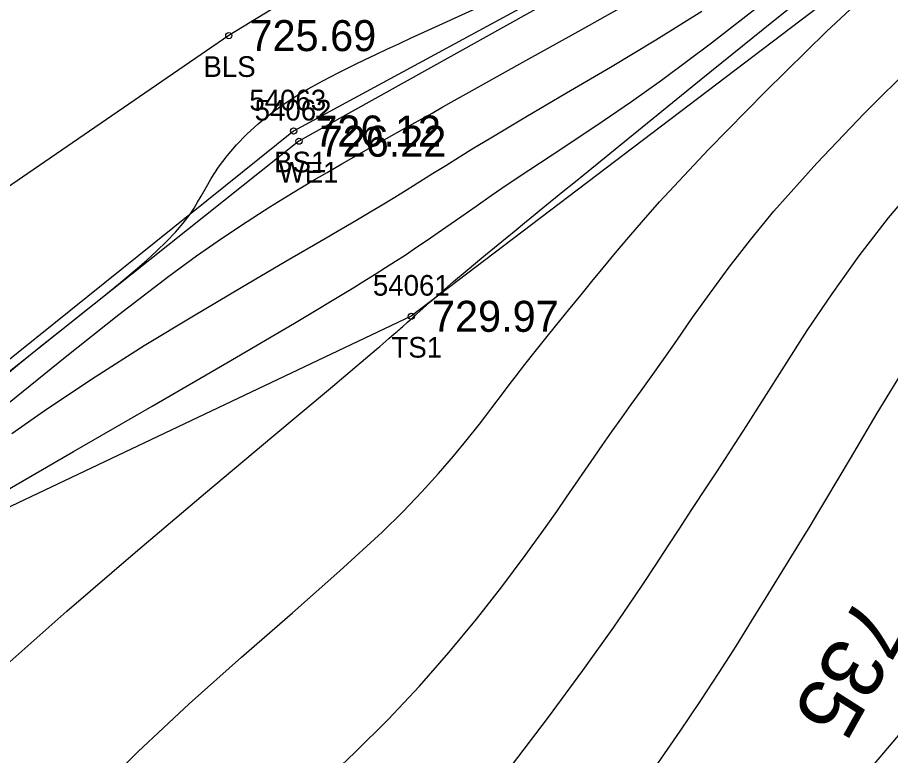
# Model space of a CAD drawing. Extents: x 1378535 to 1380697, y 997729 to 1000024.
# Drawn here: x 1379594.96 to 1379637.21, y 998876.8 to 998912.53 of the extents above; entities that cross this region are included whole.
import ezdxf

# ---------------------------------------------------------------- set-up
doc = ezdxf.new("R2010")
doc.units = 0
for name, color, linetype in [('RD_DTM_BkLn1', 7, 'Continuous'), ('RD_DTM_BkLn2', 7, 'Continuous'), ('RD_DTM_BkLn_txCode', 7, 'Continuous'), ('RD_DTM_Major1', 7, 'Continuous'), ('RD_DTM_Major1_Lbl', 7, 'Continuous'), ('RD_DTM_Minor1', 7, 'Continuous'), ('RD_EX_H2O', 7, 'Continuous'), ('RD_EX_H2O_txCode', 7, 'Continuous'), ('RD_EX_TX_H2O_ELEV', 7, 'Continuous'), ('RD_EX_TX_Misc_ELEV', 7, 'Continuous'), ('RD_SMD_Locator', 7, 'Continuous')]:
    doc.layers.add(name, color=color, linetype=linetype)

msp = doc.modelspace()

# ---------------------------------------------------------------- linework, layer by layer
at = {"layer": 'RD_DTM_BkLn1'}
msp.add_lwpolyline([(1379671.069, 998947.908), (1379636.827, 998930.955), (1379605.186, 998911.649), (1379580.097, 998894.437), (1379553.453, 998877.652)], dxfattribs=at)
at = {"layer": 'RD_DTM_BkLn2'}
for points in [[(1379671.775, 998943.782), (1379640.108, 998924.255), (1379608.322, 998907.031), (1379585.019, 998888.315), (1379555.8, 998870.974), (1379525.725, 998858.388)], [(1379674.341, 998938.659), (1379643.601, 998920.545), (1379614.018, 998898.062), (1379587.543, 998885.495), (1379561.757, 998869.277), (1379529.754, 998852.608)], [(1379679.56, 998932.013), (1379659.421, 998903.53), (1379632.901, 998872.262), (1379612.083, 998858.812), (1379587.234, 998833.516)]]:
    msp.add_lwpolyline(points, dxfattribs=at)
at = {"layer": 'RD_DTM_Major1'}
msp.add_lwpolyline([(1379594.297, 998881.082), (1379597.352, 998883.788), (1379600.677, 998886.651), (1379604.054, 998889.511), (1379607.268, 998892.208), (1379610.102, 998894.583), (1379612.339, 998896.473), (1379612.495, 998896.607), (1379612.646, 998896.737), (1379612.791, 998896.861), (1379612.93, 998896.982), (1379613.064, 998897.098), (1379613.193, 998897.211), (1379613.262, 998897.271), (1379613.33, 998897.33), (1379613.396, 998897.388), (1379613.461, 998897.445), (1379613.525, 998897.501), (1379613.587, 998897.556), (1379613.838, 998897.778), (1379614.071, 998897.986), (1379614.293, 998898.185), (1379614.722, 998898.569), (1379614.939, 998898.762), (1379615.476, 998899.233), (1379616.067, 998899.742), (1379616.717, 998900.294), (1379617.433, 998900.893), (1379618.221, 998901.544), (1379619.086, 998902.253), (1379619.501, 998902.591), (1379619.933, 998902.943), (1379620.386, 998903.311), (1379621.357, 998904.098), (1379621.879, 998904.521), (1379624.757, 998906.863), (1379628.047, 998909.536), (1379631.542, 998912.36), (1379635.038, 998915.154)], dxfattribs=at)
at = {"layer": 'RD_DTM_Minor1'}
for points in [[(1379598.427, 998874.6), (1379600.781, 998876.982), (1379603.271, 998879.309), (1379605.797, 998881.56), (1379608.261, 998883.71), (1379610.563, 998885.737), (1379612.604, 998887.616), (1379613.618, 998888.615), (1379614.526, 998889.561), (1379615.339, 998890.455), (1379616.068, 998891.3), (1379616.724, 998892.097), (1379617.317, 998892.849), (1379617.624, 998893.246), (1379617.918, 998893.632), (1379618.482, 998894.381), (1379618.759, 998894.747), (1379619.037, 998895.112), (1379619.515, 998895.729), (1379620.009, 998896.354), (1379620.524, 998896.997), (1379621.063, 998897.664), (1379621.631, 998898.363), (1379622.232, 998899.103), (1379622.75, 998899.741), (1379623.301, 998900.417), (1379623.897, 998901.135), (1379624.545, 998901.901), (1379625.255, 998902.721), (1379626.038, 998903.6), (1379628.408, 998906.142), (1379631.155, 998908.945), (1379634.11, 998911.841), (1379637.107, 998914.66)], [(1379594.555, 998893.892), (1379597.263, 998896.079), (1379599.865, 998898.15), (1379602.285, 998900.006), (1379603.629, 998900.986), (1379604.888, 998901.864), (1379606.068, 998902.652), (1379607.177, 998903.363), (1379608.222, 998904.008), (1379609.211, 998904.599), (1379609.942, 998905.026), (1379610.655, 998905.438), (1379611.365, 998905.841), (1379612.084, 998906.247), (1379612.824, 998906.663), (1379613.598, 998907.098), (1379614.055, 998907.355), (1379614.53, 998907.623), (1379615.026, 998907.903), (1379615.547, 998908.197), (1379616.095, 998908.505), (1379616.674, 998908.83), (1379619.272, 998910.279), (1379622.237, 998911.933), (1379625.404, 998913.714)], [(1379593.851, 998889.31), (1379597.678, 998891.524), (1379601.473, 998893.715), (1379605.085, 998895.811), (1379608.363, 998897.735), (1379611.158, 998899.415), (1379611.726, 998899.765), (1379612.262, 998900.099), (1379612.77, 998900.42), (1379613.254, 998900.729), (1379613.715, 998901.03), (1379614.159, 998901.323), (1379614.944, 998901.854), (1379615.693, 998902.372), (1379616.423, 998902.884), (1379617.15, 998903.396), (1379617.89, 998903.912), (1379618.659, 998904.439), (1379619.705, 998905.137), (1379620.828, 998905.874), (1379622.029, 998906.665), (1379623.311, 998907.522), (1379624.675, 998908.459), (1379626.123, 998909.49), (1379628.543, 998911.294), (1379631.085, 998913.261)], [(1379593.65, 998894.616), (1379595.053, 998895.777), (1379596.084, 998896.612), (1379597.087, 998897.412), (1379598.052, 998898.179), (1379598.974, 998898.914), (1379599.844, 998899.62), (1379600.657, 998900.299), (1379601.201, 998900.771), (1379601.709, 998901.233), (1379602.176, 998901.685), (1379602.601, 998902.13), (1379602.98, 998902.57), (1379603.311, 998903.006), (1379603.503, 998903.295), (1379603.678, 998903.584), (1379603.843, 998903.872), (1379604.165, 998904.448), (1379604.334, 998904.735), (1379604.693, 998905.283), (1379605.101, 998905.826), (1379605.557, 998906.36), (1379606.06, 998906.882), (1379606.61, 998907.387), (1379607.205, 998907.871), (1379607.773, 998908.282), (1379608.381, 998908.679), (1379609.031, 998909.067), (1379609.729, 998909.454), (1379610.477, 998909.845), (1379611.281, 998910.245), (1379611.778, 998910.486), (1379612.297, 998910.734), (1379612.842, 998910.99), (1379613.415, 998911.257), (1379614.018, 998911.536), (1379614.654, 998911.828), (1379617.168, 998912.973)], [(1379594.691, 998892.385), (1379596.417, 998893.603), (1379598.718, 998895.137), (1379601.095, 998896.642), (1379603.475, 998898.093), (1379605.786, 998899.464), (1379607.954, 998900.729), (1379609.904, 998901.864), (1379610.637, 998902.292), (1379611.327, 998902.698), (1379611.981, 998903.087), (1379612.609, 998903.463), (1379613.217, 998903.832), (1379613.813, 998904.197), (1379614.43, 998904.581), (1379615.052, 998904.971), (1379615.688, 998905.37), (1379616.349, 998905.783), (1379617.043, 998906.212), (1379617.782, 998906.661), (1379619.561, 998907.719), (1379621.537, 998908.877), (1379623.653, 998910.124), (1379625.854, 998911.449), (1379628.082, 998912.839)], [(1379609.608, 998875.348), (1379611.287, 998876.947), (1379612.901, 998878.551), (1379614.415, 998880.166), (1379615.841, 998881.793), (1379617.173, 998883.405), (1379618.405, 998884.976), (1379619.531, 998886.478), (1379620.545, 998887.885), (1379621.056, 998888.614), (1379621.537, 998889.31), (1379622.863, 998891.247), (1379623.287, 998891.857), (1379623.741, 998892.5), (1379624.2, 998893.141), (1379624.666, 998893.788), (1379625.143, 998894.45), (1379625.633, 998895.137), (1379626.141, 998895.856), (1379626.862, 998896.893), (1379627.635, 998898.005), (1379628.477, 998899.188), (1379629.403, 998900.443), (1379630.429, 998901.765), (1379631.571, 998903.154), (1379633.639, 998905.483), (1379635.93, 998907.885), (1379638.331, 998910.269)], [(1379618.874, 998876.305), (1379620.665, 998878.658), (1379622.326, 998880.919), (1379623.812, 998883.016), (1379624.545, 998884.083), (1379625.221, 998885.088), (1379625.85, 998886.039), (1379626.443, 998886.945), (1379627.01, 998887.816), (1379627.562, 998888.66), (1379628.386, 998889.906), (1379628.802, 998890.536), (1379629.227, 998891.182), (1379629.664, 998891.852), (1379630.115, 998892.555), (1379632.072, 998895.657), (1379633.179, 998897.373), (1379634.382, 998899.158), (1379635.689, 998900.984), (1379637.109, 998902.822), (1379638.866, 998904.898)], [(1379625.038, 998875.111), (1379627.031, 998877.977), (1379628.027, 998879.459), (1379628.923, 998880.827), (1379629.738, 998882.101), (1379630.489, 998883.302), (1379631.197, 998884.448), (1379632.948, 998887.306), (1379633.314, 998887.908), (1379633.691, 998888.531), (1379634.081, 998889.18), (1379635.268, 998891.18), (1379636.571, 998893.368), (1379637.974, 998895.671)]]:
    msp.add_lwpolyline(points, dxfattribs=at)
at = {"layer": 'RD_EX_H2O'}
msp.add_lwpolyline([(1379671.834, 998943.202), (1379640, 998924.062), (1379608.579, 998906.539), (1379585.103, 998887.86), (1379555.99, 998870.389), (1379525.834, 998856.734)], dxfattribs=at)
at = {"layer": 'RD_SMD_Locator'}
for centre in [(1379605.186, 998911.649), (1379608.322, 998907.031), (1379608.579, 998906.539), (1379614.018, 998898.062)]:
    msp.add_circle(centre, 0.15, dxfattribs=at)

# ---------------------------------------------------------------- texts
at = {"layer": 'RD_DTM_BkLn_txCode'}
for s, p in [('BLS', (1379603.958, 998909.649)), ('54063', (1379606.18, 998908.031)), ('BS1', (1379607.377, 998905.031)), ('54061', (1379612.16, 998899.062)), ('TS1', (1379613.057, 998896.062))]:
    msp.add_text(s, height=1, dxfattribs=at).set_placement(p)
at = {"layer": 'RD_DTM_Major1_Lbl'}
msp.add_text('735', height=3, rotation=240.7806, dxfattribs=at).set_placement((1379635.7, 998884.669))
at = {"layer": 'RD_EX_H2O_txCode'}
for s, p in [('54062', (1379606.437, 998907.539)), ('WE1', (1379607.595, 998904.539))]:
    msp.add_text(s, height=1, dxfattribs=at).set_placement(p)
at = {"layer": 'RD_EX_TX_H2O_ELEV'}
msp.add_text('726.22', height=1.5, dxfattribs=at).set_placement((1379609.579, 998905.789))
at = {"layer": 'RD_EX_TX_Misc_ELEV'}
for s, p in [('725.69', (1379606.186, 998910.899)), ('726.12', (1379609.322, 998906.281)), ('729.97', (1379615.018, 998897.312))]:
    msp.add_text(s, height=1.5, dxfattribs=at).set_placement(p)

doc.saveas('drawing.dxf')
